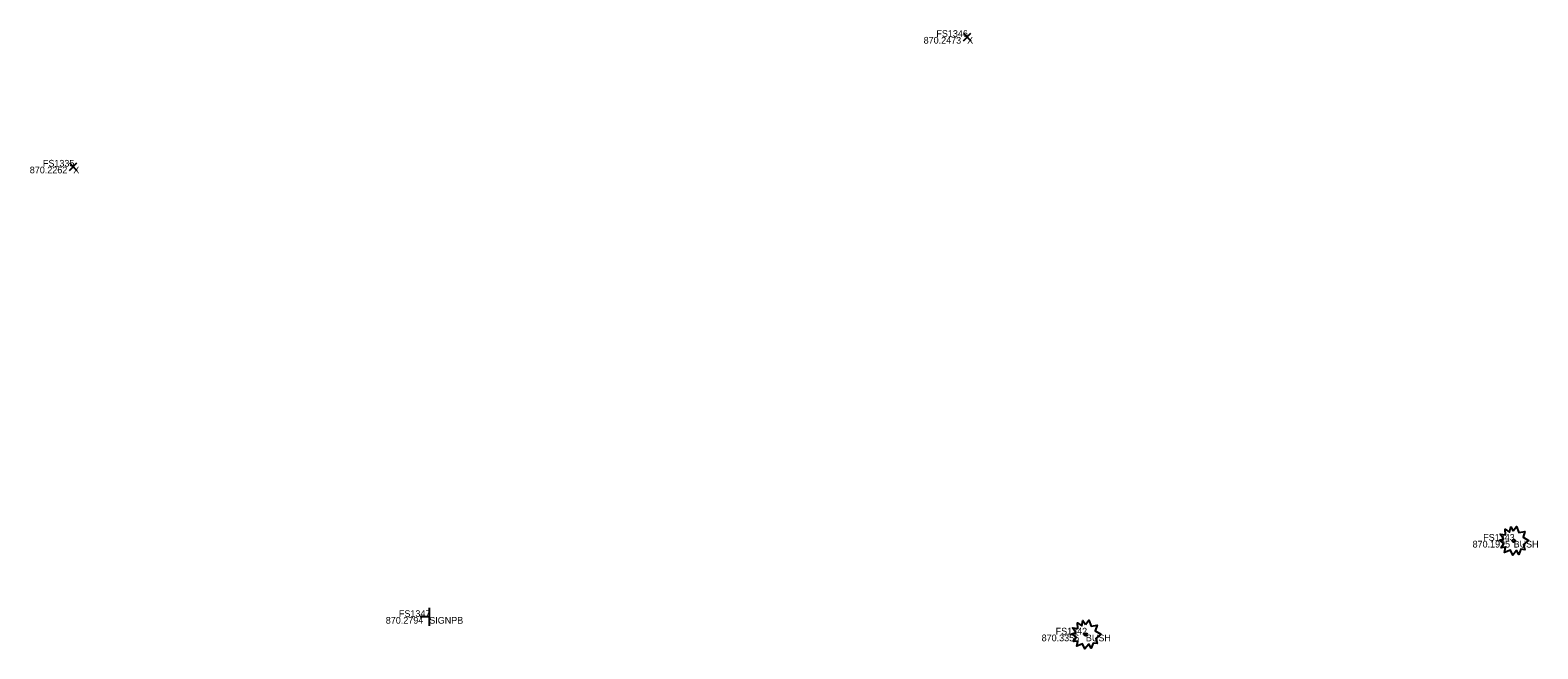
# Model space of a CAD drawing. Extents: x 1479425 to 1480294, y 379351 to 380102.
# Drawn here: x 1479624.05 to 1479637.5, y 379862.6 to 379868.12 of the extents above; entities that cross this region are included whole.
import ezdxf

# ---------------------------------------------------------------- set-up
doc = ezdxf.new("R2010")
doc.units = 0
for name, color, linetype in [('SN_X_Public', 7, 'Continuous'), ('SV_X_Random_Point', 7, 'Continuous'), ('SV_X_Text_Comment', 7, 'Continuous'), ('SV_X_Text_Elevation', 7, 'Continuous'), ('SV_X_Text_Name', 7, 'Continuous'), ('VG_X_Cells', 7, 'Continuous')]:
    doc.layers.add(name, color=color, linetype=linetype)

msp = doc.modelspace()

# ---------------------------------------------------------------- linework, layer by layer
at = {"layer": 'SN_X_Public'}
for p, q in [((1479627.61, 379862.962), (1479627.61, 379862.802)), ((1479627.61, 379862.882), (1479627.53, 379862.882))]:
    msp.add_line(p, q, dxfattribs=at)
at = {"layer": 'SV_X_Random_Point'}
for p, q in [((1479632.377, 379868.027), (1479632.443, 379868.094)), ((1479632.377, 379868.094), (1479632.443, 379868.027)), ((1479624.4, 379866.869), (1479624.466, 379866.936)), ((1479624.4, 379866.936), (1479624.466, 379866.869))]:
    msp.add_line(p, q, dxfattribs=at)
at = {"layer": 'VG_X_Cells'}
for points in [[(1479637.283, 379863.652), (1479637.313, 379863.689), (1479637.334, 379863.636), (1479637.388, 379863.645), (1479637.371, 379863.595), (1479637.419, 379863.565), (1479637.376, 379863.528), (1479637.388, 379863.482), (1479637.351, 379863.486), (1479637.334, 379863.44), (1479637.313, 379863.475), (1479637.279, 379863.434), (1479637.258, 379863.478), (1479637.207, 379863.457), (1479637.216, 379863.504), (1479637.176, 379863.5), (1479637.199, 379863.539), (1479637.161, 379863.568), (1479637.198, 379863.581), (1479637.167, 379863.621), (1479637.214, 379863.615), (1479637.213, 379863.667), (1479637.25, 379863.639), (1479637.261, 379863.688), (1479637.283, 379863.652)], [(1479633.466, 379862.815), (1479633.496, 379862.852), (1479633.517, 379862.799), (1479633.571, 379862.808), (1479633.554, 379862.758), (1479633.602, 379862.728), (1479633.559, 379862.691), (1479633.571, 379862.646), (1479633.534, 379862.649), (1479633.517, 379862.603), (1479633.496, 379862.638), (1479633.462, 379862.597), (1479633.441, 379862.641), (1479633.39, 379862.62), (1479633.399, 379862.667), (1479633.359, 379862.663), (1479633.382, 379862.702), (1479633.344, 379862.731), (1479633.381, 379862.744), (1479633.35, 379862.784), (1479633.397, 379862.779), (1479633.396, 379862.831), (1479633.433, 379862.802), (1479633.444, 379862.851), (1479633.466, 379862.815)]]:
    msp.add_lwpolyline(points, dxfattribs=at)
for centre in [(1479637.287, 379863.562), (1479633.47, 379862.725)]:
    msp.add_circle(centre, 0.0115, dxfattribs=at)

# ---------------------------------------------------------------- texts
at = {"layer": 'SV_X_Text_Comment'}
for s, p in [('X', (1479632.41, 379868.001)), ('X', (1479624.433, 379866.843)), ('BUSH', (1479637.287, 379863.502)), ('SIGNPB', (1479627.61, 379862.822)), ('BUSH', (1479633.47, 379862.665))]:
    msp.add_text(s, height=0.06, dxfattribs=at).set_placement(p)
at = {"layer": 'SV_X_Text_Elevation'}
for s, p in [('870.2473', (1479632.022, 379868.001)), ('870.2262', (1479624.045, 379866.843)), ('870.1925', (1479636.921, 379863.502)), ('870.2794', (1479627.222, 379862.822)), ('870.3356', (1479633.075, 379862.665))]:
    msp.add_text(s, height=0.06, dxfattribs=at).set_placement(p)
at = {"layer": 'SV_X_Text_Name'}
for s, p in [('FS1346', (1479632.136, 379868.061)), ('FS1335', (1479624.162, 379866.903)), ('FS1343', (1479637.016, 379863.562)), ('FS1347', (1479627.339, 379862.882)), ('FS1342', (1479633.2, 379862.725))]:
    msp.add_text(s, height=0.06, dxfattribs=at).set_placement(p)

doc.saveas('drawing.dxf')
